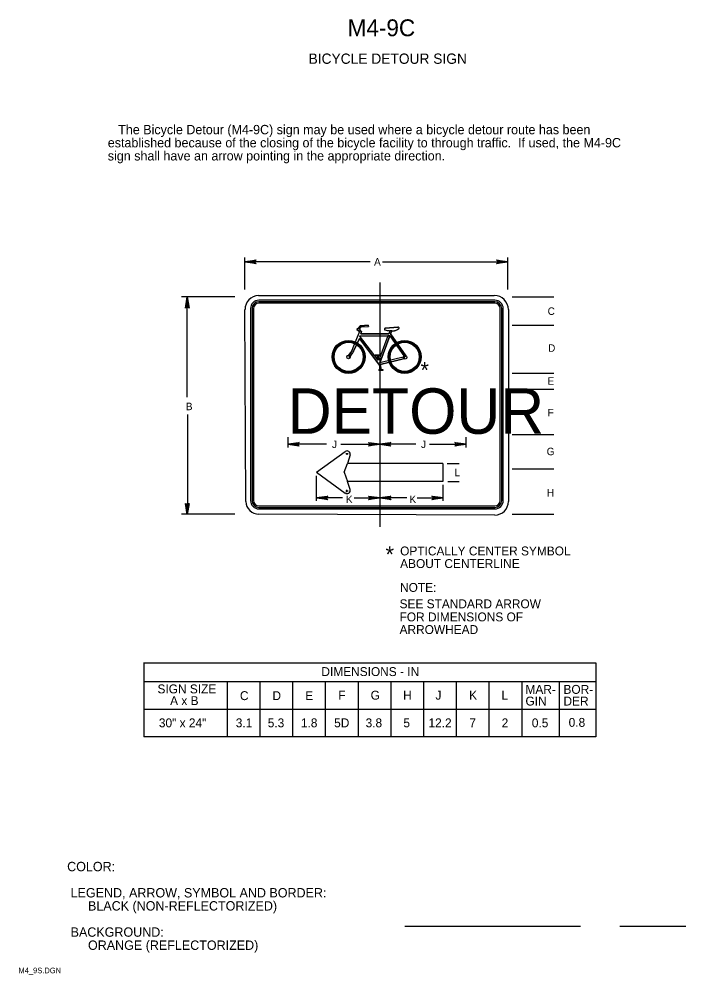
# Model space of a CAD drawing. Extents: x 0.012 to 0.191, y 0.004 to 0.259.
import ezdxf

# ---------------------------------------------------------------- set-up
doc = ezdxf.new("R2010")
doc.units = 0
for name, color, linetype in [('1', 7, 'Continuous'), ('2', 7, 'Continuous'), ('3', 7, 'Continuous')]:
    doc.layers.add(name, color=color, linetype=linetype)

# ---------------------------------------------------------------- blocks, each defined once
blk = doc.blocks.new('RARROW')
at = {"layer": '3'}
for p, q in [((-2.156, 0.28500000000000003), (-2.2665, 0.384625)), ((-2.2665, 0.384625), (0, 0)), ((0, 0), (-2.2665, -0.379125)), ((-2.156, 0.28500000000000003), (-2.075625, 0.12075)), ((0, 0), (-2.156, 0.28500000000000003)), ((-2.14975, -0.2705), (0, 0)), ((-2.075625, 0.12075), (0, 0)), ((0, 0), (-2.074, -0.108)), ((-2.2665, -0.379125), (-2.14975, -0.2705)), ((-2.074, -0.108), (-2.14975, -0.2705))]:
    blk.add_line(p, q, dxfattribs=at)

msp = doc.modelspace()

# ---------------------------------------------------------------- linework, layer by layer
at = {"layer": '1'}
for p, q in [((0.10875, 0.18887500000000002), (0.10875, 0.12356034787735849)), ((0.11543984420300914, 0.01694517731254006), (0.1624214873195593, 0.01694517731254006)), ((0.17295324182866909, 0.01694517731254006), (0.19056484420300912, 0.01694517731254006))]:
    msp.add_line(p, q, dxfattribs=at)
at = {"layer": '2'}
for p, q in [((0.076375, 0.185375), (0.139375, 0.185375)), ((0.1395, 0.184125), (0.0765, 0.184125)), ((0.073, 0.130375), (0.07275, 0.181625)), ((0.07425, 0.181875), (0.07425, 0.130625)), ((0.07465000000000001, 0.181875), (0.07465000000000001, 0.130625)), ((0.07505, 0.181875), (0.07505, 0.130625)), ((0.1395, 0.183725), (0.0765, 0.183725)), ((0.1395, 0.183325), (0.0765, 0.183325)), ((0.14095, 0.130625), (0.14095, 0.181875)), ((0.14135, 0.130625), (0.14135, 0.181875)), ((0.14175000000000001, 0.130625), (0.14175000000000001, 0.181875)), ((0.143125, 0.181625), (0.143125, 0.130375)), ((0.0765, 0.129175), (0.1395, 0.129175)), ((0.0765, 0.128775), (0.1395, 0.128775)), ((0.0765, 0.128375), (0.1395, 0.128375)), ((0.1395, 0.12675), (0.0765, 0.127)), ((0.04576275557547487, 0.08737500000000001), (0.04576275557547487, 0.06749703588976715)), ((0.04576275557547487, 0.0873220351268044), (0.16651708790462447, 0.0873220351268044)), ((0.16651708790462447, 0.0873220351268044), (0.16651708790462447, 0.06749703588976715)), ((0.16651708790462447, 0.08219703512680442), (0.04576275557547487, 0.08219703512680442)), ((0.06796555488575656, 0.08219416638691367), (0.06796555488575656, 0.06749703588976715)), ((0.07671555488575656, 0.08219416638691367), (0.07671555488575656, 0.06749703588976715)), ((0.08546555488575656, 0.08219416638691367), (0.08546555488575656, 0.06749703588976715)), ((0.09421555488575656, 0.08219416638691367), (0.09421555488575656, 0.06749703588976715)), ((0.10296555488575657, 0.08219416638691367), (0.10296555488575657, 0.06749703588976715)), ((0.11171555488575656, 0.08219416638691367), (0.11171555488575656, 0.06749703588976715)), ((0.12046555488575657, 0.08219416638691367), (0.12046555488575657, 0.06749703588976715)), ((0.1292155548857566, 0.08219416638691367), (0.1292155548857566, 0.06749703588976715)), ((0.13789974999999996, 0.08219416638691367), (0.13789974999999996, 0.06749703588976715)), ((0.14674055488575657, 0.08219416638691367), (0.14674055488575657, 0.06749703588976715)), ((0.15670470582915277, 0.08219416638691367), (0.15670470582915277, 0.06749703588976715)), ((0.16651708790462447, 0.07484703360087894), (0.04576275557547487, 0.07484703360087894)), ((0.16651708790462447, 0.06749703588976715), (0.04576275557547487, 0.06749703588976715))]:
    msp.add_line(p, q, dxfattribs=at)
for centre, radius, start, end in [((0.07647908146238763, 0.181684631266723), 0.00368802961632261, 90.97102222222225, 180.97102222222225), ((0.07648591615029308, 0.1818871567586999), 0.002235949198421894, 90.31151666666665, 180.31151666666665), ((0.1393750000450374, 0.18162500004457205), 0.0037499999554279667, 0, 90), ((0.13950000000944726, 0.1818750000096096), 0.0022499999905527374, 0, 90), ((0.07648591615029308, 0.1818871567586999), 0.0018359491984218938, 90.31151666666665, 180.31151666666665), ((0.07648591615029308, 0.1818871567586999), 0.0014359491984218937, 90.31151666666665, 180.31151666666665), ((0.13950000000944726, 0.1818750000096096), 0.0018499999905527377, 0, 90), ((0.13950000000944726, 0.1818750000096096), 0.0014499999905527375, 0, 90), ((0.07643750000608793, 0.13043750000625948), 0.0034380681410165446, 181.04162777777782, 271.0416277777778), ((0.07650000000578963, 0.13062500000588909), 0.002250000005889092, 180, 270), ((0.07650000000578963, 0.13062500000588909), 0.001850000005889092, 180, 270), ((0.07650000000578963, 0.13062500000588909), 0.0014500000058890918, 180, 270), ((0.13949999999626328, 0.130625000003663), 0.00225000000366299, 270, 0), ((0.13949999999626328, 0.130625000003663), 0.0018500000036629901, 270, 0), ((0.13949999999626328, 0.130625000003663), 0.00145000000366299, 270, 0), ((0.13949999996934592, 0.13037500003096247), 0.003625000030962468, 270, 0)]:
    msp.add_arc(centre, radius, start, end, dxfattribs=at)
at = {"layer": '3'}
for p, q in [((0.07274167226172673, 0.18700966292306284), (0.07274167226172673, 0.19550966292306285)), ((0.10625, 0.194375), (0.07275, 0.194375)), ((0.1095, 0.194375), (0.14300000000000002, 0.194375)), ((0.14299612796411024, 0.18700966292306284), (0.14299612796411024, 0.19550966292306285)), ((0.07008239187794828, 0.18499713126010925), (0.0557621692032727, 0.18499713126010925)), ((0.05733301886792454, 0.15821797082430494), (0.05733301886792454, 0.185)), ((0.144125, 0.185), (0.15525, 0.185)), ((0.10267941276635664, 0.17630164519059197), (0.10325303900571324, 0.17687527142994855)), ((0.10331677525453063, 0.17572801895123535), (0.10267941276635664, 0.17630164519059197)), ((0.10325303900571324, 0.17687527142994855), (0.10338051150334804, 0.17713021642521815)), ((0.10331677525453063, 0.17636538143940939), (0.10357172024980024, 0.17662032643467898)), ((0.10389040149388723, 0.1757917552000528), (0.10331677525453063, 0.17636538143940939)), ((0.10338051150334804, 0.17713021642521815), (0.10350798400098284, 0.17725768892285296)), ((0.10350798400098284, 0.17725768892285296), (0.10369919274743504, 0.17732142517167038)), ((0.10357172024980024, 0.17662032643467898), (0.10376292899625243, 0.17700274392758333)), ((0.10363545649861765, 0.1767477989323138), (0.10376292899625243, 0.17700274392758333)), ((0.10369919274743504, 0.17732142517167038), (0.10567501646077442, 0.1774488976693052)), ((0.10376292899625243, 0.17700274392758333), (0.10573875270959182, 0.17713021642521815)), ((0.10567501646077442, 0.1774488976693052), (0.10573875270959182, 0.17713021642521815)), ((0.1102640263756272, 0.17662032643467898), (0.11364204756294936, 0.17693900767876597)), ((0.144125, 0.1774488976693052), (0.15525, 0.1774488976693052)), ((0.10331677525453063, 0.17572801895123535), (0.10159589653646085, 0.17139395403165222)), ((0.10331677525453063, 0.17387966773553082), (0.10210578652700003, 0.1712027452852)), ((0.1086706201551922, 0.16680494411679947), (0.10331677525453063, 0.17387966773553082)), ((0.10338051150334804, 0.1746445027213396), (0.11096512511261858, 0.1746445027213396)), ((0.1083519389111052, 0.16814340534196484), (0.10338051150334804, 0.1746445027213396)), ((0.10389040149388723, 0.1757917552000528), (0.10369919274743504, 0.1751543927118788)), ((0.10369919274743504, 0.1751543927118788), (0.11115633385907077, 0.1751543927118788)), ((0.11096512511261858, 0.1746445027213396), (0.10854314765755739, 0.16807966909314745)), ((0.11147501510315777, 0.1745807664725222), (0.108798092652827, 0.16744230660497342)), ((0.11147501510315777, 0.1759192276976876), (0.11115633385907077, 0.1751543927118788)), ((0.11147501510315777, 0.1745807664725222), (0.11536292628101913, 0.16897197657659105)), ((0.11198490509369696, 0.1759192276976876), (0.11166622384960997, 0.1751543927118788)), ((0.11166622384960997, 0.1751543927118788), (0.11574534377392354, 0.16929065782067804)), ((0.10758710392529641, 0.16948186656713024), (0.10803325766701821, 0.16948186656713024)), ((0.10758710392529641, 0.16948186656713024), (0.10758710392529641, 0.16935439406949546)), ((0.10758710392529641, 0.16935439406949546), (0.10803325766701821, 0.16935439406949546)), ((0.10803325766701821, 0.16948186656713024), (0.1087343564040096, 0.16948186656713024)), ((0.10803325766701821, 0.16935439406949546), (0.1083519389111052, 0.16814340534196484)), ((0.1082244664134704, 0.16935439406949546), (0.10854314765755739, 0.16807966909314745)), ((0.1082244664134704, 0.16935439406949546), (0.1087343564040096, 0.16935439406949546)), ((0.1087343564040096, 0.16948186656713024), (0.1087343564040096, 0.16935439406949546)), ((0.11536292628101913, 0.16897197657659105), (0.108798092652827, 0.16744230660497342)), ((0.1086706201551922, 0.16680494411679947), (0.10898930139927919, 0.16553021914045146)), ((0.10875, 0.16557287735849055), (0.10875, 0.16657287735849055)), ((0.11523545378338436, 0.16846208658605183), (0.10886182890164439, 0.16693241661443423)), ((0.10886182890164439, 0.16693241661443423), (0.1091805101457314, 0.16553021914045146)), ((0.10854314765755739, 0.16553021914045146), (0.10898930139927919, 0.16553021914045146)), ((0.10854314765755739, 0.16540274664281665), (0.10854314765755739, 0.16553021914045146)), ((0.10854314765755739, 0.16540274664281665), (0.10898930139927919, 0.16540274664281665)), ((0.10898930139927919, 0.16540274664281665), (0.10969040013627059, 0.16540274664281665)), ((0.1091805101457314, 0.16553021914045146), (0.10969040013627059, 0.16553021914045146)), ((0.10969040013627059, 0.16540274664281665), (0.10969040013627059, 0.16553021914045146)), ((0.144125, 0.1645948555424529), (0.15525, 0.1645948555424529)), ((0.144125, 0.1603503), (0.15525, 0.1603503)), ((0.05737460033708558, 0.1535789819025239), (0.05737460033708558, 0.12699713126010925)), ((0.144125, 0.1482703), (0.15525, 0.1482703)), ((0.08425993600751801, 0.14477478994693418), (0.08425993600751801, 0.1475572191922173)), ((0.0945422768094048, 0.1456405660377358), (0.08425993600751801, 0.1456405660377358)), ((0.0983491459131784, 0.1456405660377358), (0.10875, 0.1456405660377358)), ((0.11844587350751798, 0.1456405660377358), (0.10875, 0.1456405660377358)), ((0.12210097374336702, 0.1456405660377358), (0.13119375, 0.1456405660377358)), ((0.1318394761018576, 0.14477478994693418), (0.1318394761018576, 0.1475572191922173)), ((0.09186034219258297, 0.1382025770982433), (0.09952695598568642, 0.14370253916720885)), ((0.10036028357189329, 0.14311920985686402), (0.09969362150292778, 0.14311920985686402)), ((0.1002769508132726, 0.14310866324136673), (0.09969362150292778, 0.14310866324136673)), ((0.09994361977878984, 0.14327532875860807), (0.09994361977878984, 0.14285866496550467)), ((0.09994361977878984, 0.1432025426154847), (0.09994361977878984, 0.14286921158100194)), ((0.09927695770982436, 0.13820257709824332), (0.10011028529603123, 0.14053589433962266)), ((0.10086028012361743, 0.14278587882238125), (0.10011028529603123, 0.14053589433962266)), ((0.12566667, 0.14053589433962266), (0.10011028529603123, 0.14053589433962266)), ((0.12566667, 0.14053589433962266), (0.12566667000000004, 0.13570259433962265)), ((0.12675996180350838, 0.14053589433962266), (0.12999769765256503, 0.14053589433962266)), ((0.09186034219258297, 0.1382025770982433), (0.09952695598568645, 0.1326192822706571)), ((0.09927695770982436, 0.13820257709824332), (0.10011028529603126, 0.13570259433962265)), ((0.144125, 0.1390703), (0.15525, 0.1390703)), ((0.09186735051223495, 0.1305061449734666), (0.09186735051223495, 0.1372582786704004)), ((0.10086028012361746, 0.1335359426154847), (0.10011028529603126, 0.13570259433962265)), ((0.12566667, 0.13570259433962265), (0.10011028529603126, 0.13570259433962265)), ((0.12696232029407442, 0.13570259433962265), (0.12999769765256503, 0.13570259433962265)), ((0.10036028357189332, 0.13311927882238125), (0.09969362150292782, 0.13311927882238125)), ((0.10027695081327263, 0.13310873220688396), (0.09969362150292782, 0.13310873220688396)), ((0.09994361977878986, 0.13303594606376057), (0.09994361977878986, 0.13345260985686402)), ((0.09994361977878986, 0.1328587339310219), (0.09994361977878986, 0.13335873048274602)), ((0.12572445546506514, 0.1305061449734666), (0.12572445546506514, 0.13481732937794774)), ((0.0988234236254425, 0.13132370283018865), (0.09186735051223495, 0.13132370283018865)), ((0.1018967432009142, 0.13132370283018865), (0.10875, 0.13132370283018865)), ((0.11601124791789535, 0.13132370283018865), (0.10875, 0.13132370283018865)), ((0.11876838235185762, 0.13132370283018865), (0.12572445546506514, 0.13132370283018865)), ((0.07008239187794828, 0.12699713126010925), (0.0557621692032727, 0.12699713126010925)), ((0.144125, 0.1269903), (0.15525, 0.1269903))]:
    msp.add_line(p, q, dxfattribs=at)
for points in [[(0.11574534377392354, 0.16929065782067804), (0.11166622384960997, 0.1751543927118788), (0.11198490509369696, 0.1759192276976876), (0.11147501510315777, 0.1759192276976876), (0.11115633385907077, 0.1751543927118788), (0.10369919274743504, 0.1751543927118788), (0.10389040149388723, 0.1757917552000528), (0.10331677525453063, 0.17636538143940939), (0.10357172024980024, 0.17662032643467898), (0.10376292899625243, 0.17700274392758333), (0.10573875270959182, 0.17713021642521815), (0.10567501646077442, 0.1774488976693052), (0.10369919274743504, 0.17732142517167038), (0.10350798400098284, 0.17725768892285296), (0.10338051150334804, 0.17713021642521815), (0.10325303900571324, 0.17687527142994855), (0.10267941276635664, 0.17630164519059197), (0.10331677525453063, 0.17572801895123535), (0.10159589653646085, 0.17139395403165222), (0.10140468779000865, 0.1708203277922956), (0.10121347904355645, 0.17043791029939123), (0.10083106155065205, 0.16986428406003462), (0.10038490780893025, 0.16935439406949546), (0.10083106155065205, 0.16909944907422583), (0.10102227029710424, 0.16935439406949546), (0.10146842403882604, 0.16986428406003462), (0.10185084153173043, 0.17056538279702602), (0.10210578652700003, 0.1712027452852), (0.10331677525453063, 0.17387966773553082), (0.1086706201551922, 0.16680494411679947), (0.10898930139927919, 0.16553021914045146), (0.10854314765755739, 0.16553021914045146), (0.10854314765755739, 0.16540274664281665), (0.10969040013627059, 0.16540274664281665), (0.10969040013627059, 0.16553021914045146), (0.1091805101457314, 0.16553021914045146), (0.10886182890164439, 0.16693241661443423), (0.11536292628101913, 0.16852582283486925), (0.11536292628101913, 0.16897197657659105), (0.108798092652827, 0.16744230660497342), (0.11147501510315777, 0.1745807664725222), (0.11096512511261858, 0.1746445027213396), (0.10854314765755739, 0.16807966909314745), (0.1082244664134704, 0.16935439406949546), (0.1087343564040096, 0.16935439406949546), (0.1087343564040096, 0.16948186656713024), (0.10758710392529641, 0.16948186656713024), (0.10758710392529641, 0.16935439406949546), (0.10803325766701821, 0.16935439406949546), (0.1083519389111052, 0.16814340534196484), (0.10338051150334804, 0.1746445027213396), (0.11147501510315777, 0.1745807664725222), (0.11536292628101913, 0.16897197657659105)], [(0.11364204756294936, 0.17693900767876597), (0.1102640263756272, 0.17662032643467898), (0.11020029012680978, 0.17662032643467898), (0.110072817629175, 0.17655659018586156), (0.11000908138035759, 0.17642911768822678), (0.110072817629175, 0.17623790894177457), (0.11020029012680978, 0.17617417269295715), (0.11071018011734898, 0.1760467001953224), (0.11153875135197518, 0.1759192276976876), (0.11236732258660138, 0.1759192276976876), (0.11274974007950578, 0.17598296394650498), (0.11294094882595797, 0.1760467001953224), (0.11319589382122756, 0.17611043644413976), (0.11351457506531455, 0.17630164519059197), (0.11383325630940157, 0.17649285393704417), (0.11389699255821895, 0.17655659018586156), (0.11396072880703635, 0.17662032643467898), (0.11396072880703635, 0.1767477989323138), (0.11389699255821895, 0.17687527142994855), (0.11376952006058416, 0.17693900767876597)]]:
    msp.add_lwpolyline(points, close=True, dxfattribs=at)
for centre, radius in [((0.10044849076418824, 0.1689904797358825), 0.004397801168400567), ((0.10044849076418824, 0.1689904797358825), 0.004346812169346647), ((0.10044849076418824, 0.1689904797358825), 0.004295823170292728), ((0.10044849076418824, 0.1689904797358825), 0.004244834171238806), ((0.10044849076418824, 0.1689904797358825), 0.004193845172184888), ((0.10044849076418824, 0.1689904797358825), 0.004142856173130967), ((0.10044849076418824, 0.1689904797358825), 0.004091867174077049), ((0.10044849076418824, 0.1689904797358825), 0.004040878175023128), ((0.10044849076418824, 0.1689904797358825), 0.00398988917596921), ((0.10044849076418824, 0.1689904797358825), 0.003938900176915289), ((0.10044849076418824, 0.1689904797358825), 0.00388791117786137), ((0.11542650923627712, 0.1689904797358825), 0.004397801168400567), ((0.11542650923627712, 0.1689904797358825), 0.004346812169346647), ((0.11542650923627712, 0.1689904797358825), 0.004295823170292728), ((0.11542650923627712, 0.1689904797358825), 0.004244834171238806), ((0.11542650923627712, 0.1689904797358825), 0.004193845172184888), ((0.11542650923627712, 0.1689904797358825), 0.004142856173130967), ((0.11542650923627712, 0.1689904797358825), 0.004091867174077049), ((0.11542650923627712, 0.1689904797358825), 0.004040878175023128), ((0.11542650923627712, 0.1689904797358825), 0.00398988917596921), ((0.11542650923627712, 0.1689904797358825), 0.003938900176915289), ((0.11542650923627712, 0.1689904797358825), 0.00388791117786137), ((0.10044849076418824, 0.1689904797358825), 0.00048540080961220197), ((0.11555398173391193, 0.16886300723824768), 0.00048540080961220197)]:
    msp.add_circle(centre, radius, dxfattribs=at)
for centre, radius, start, end in [((0.11023200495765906, 0.1764157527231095), 0.00022534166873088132, 81.86989722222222, 261.8698972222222), ((0.11217596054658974, 0.18368965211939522), 0.00775296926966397, 255.23545833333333, 270.9420861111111), ((0.11207456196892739, 0.17882034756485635), 0.002891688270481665, 274.53958888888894, 309.0632305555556), ((0.09646926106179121, 0.17319425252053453), 0.005461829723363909, 312.61111111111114, 340.70747500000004), ((0.09646926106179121, 0.17319425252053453), 0.0059717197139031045, 312.61111111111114, 340.70747500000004), ((0.10004468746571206, 0.1430170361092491), 0.0008506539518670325, 343.4926194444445, 127.49033611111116), ((0.10004659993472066, 0.13331141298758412), 0.0008506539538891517, 232.50966388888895, 16.507380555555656)]:
    msp.add_arc(centre, radius, start, end, dxfattribs=at)

# ---------------------------------------------------------------- block references
at = {"layer": '3', "xscale": 0.0013236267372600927, "yscale": 0.001309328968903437}
for p, rotation in [((0.07275, 0.194375), 180), ((0.05733301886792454, 0.185), 90), ((0.08425993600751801, 0.1456405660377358), 180), ((0.10875, 0.1456405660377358), 180), ((0.09186735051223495, 0.13132370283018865), 180), ((0.10875, 0.13132370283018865), 180), ((0.05733301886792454, 0.12687500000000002), -90)]:
    msp.add_blockref('RARROW', p, dxfattribs=dict(at, rotation=rotation))
for p in [(0.14300000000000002, 0.194375), (0.10875, 0.1456405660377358), (0.1318394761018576, 0.1456405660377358), (0.10875, 0.13132370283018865), (0.12572445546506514, 0.13132370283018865)]:
    msp.add_blockref('RARROW', p, dxfattribs=at)

# ---------------------------------------------------------------- texts
at = {"layer": '1'}
for s, height, p in [('M4-9C', 0.0045000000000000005, (0.10018477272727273, 0.254625)), ('BICYCLE DETOUR SIGN', 0.00275025, (0.0897534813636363, 0.24725)), ('*', 0.004332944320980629, (0.11965541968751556, 0.16330399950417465)), ('DETOUR', 0.01213425, (0.08418428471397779, 0.14844787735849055)), ('*', 0.004332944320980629, (0.11032163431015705, 0.11408029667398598)), ('OPTICALLY CENTER SYMBOL', 0.0023752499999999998, (0.11421851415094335, 0.1159663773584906)), ('ABOUT CENTERLINE', 0.0023752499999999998, (0.11421851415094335, 0.11259112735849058)), ('NOTE:', 0.0023752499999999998, (0.11419174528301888, 0.10622712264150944)), ('SEE STANDARD ARROW', 0.0023752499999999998, (0.11406674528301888, 0.10185212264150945)), ('FOR DIMENSIONS OF', 0.0023752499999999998, (0.11406674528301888, 0.09835212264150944)), ('ARROWHEAD', 0.0023752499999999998, (0.11406674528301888, 0.09497712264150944)), ('MAR-', 0.0023752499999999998, (0.14770691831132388, 0.079)), ('BOR-', 0.0023752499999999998, (0.15785868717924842, 0.079)), ('GIN', 0.0023752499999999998, (0.14770691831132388, 0.075875)), ('DER', 0.0023752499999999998, (0.15785868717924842, 0.075875)), ('COLOR:', 0.0024997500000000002, (0.02525, 0.031624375)), (' LEGEND, ARROW, SYMBOL AND BORDER:', 0.0024997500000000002, (0.02525, 0.024624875)), ('      BLACK (NON-REFLECTORIZED)', 0.0024997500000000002, (0.02525, 0.021125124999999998)), (' BACKGROUND:', 0.0024997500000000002, (0.02525, 0.014125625)), ('      ORANGE (REFLECTORIZED)', 0.0024997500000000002, (0.02525, 0.010625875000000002)), ('M4_9S.DGN', 0.0015, (0.01225, 0.004375))]:
    msp.add_text(s, height=height, dxfattribs=at).set_placement(p)
at = {"layer": '2'}
for s, height, p in [('   The Bicycle Detour (M4-9C) sign may be used where a bicycle detour route has been ', 0.0024997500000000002, (0.03610613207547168, 0.22843891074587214)), ('established because of the closing of the bicycle facility to through traffic.  If used, the M4-9C ', 0.0024997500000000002, (0.03610613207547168, 0.22493916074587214)), ('sign shall have an arrow pointing in the appropriate direction. ', 0.0024997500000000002, (0.03610613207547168, 0.22143941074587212)), ('DIMENSIONS - IN', 0.0023752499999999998, (0.0931822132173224, 0.08375)), ('SIGN SIZE', 0.0023752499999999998, (0.04938775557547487, 0.079125)), ('C', 0.0023752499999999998, (0.07141595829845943, 0.07732417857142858)), ('D', 0.0023752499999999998, (0.08009732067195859, 0.07732417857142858)), ('E', 0.0023752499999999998, (0.08887984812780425, 0.07732417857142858)), ('F', 0.0023752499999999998, (0.09768519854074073, 0.07744917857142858)), ('G', 0.0023752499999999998, (0.10633934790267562, 0.07744917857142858)), ('H', 0.0023752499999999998, (0.11501546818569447, 0.07744917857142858)), ('J', 0.0023752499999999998, (0.12366164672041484, 0.07744917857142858)), ('K', 0.0023752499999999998, (0.13265052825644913, 0.07744917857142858)), ('L', 0.0023752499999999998, (0.14127927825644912, 0.07744917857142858)), ('A x B', 0.0023752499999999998, (0.05276275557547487, 0.076))]:
    msp.add_text(s, height=height, dxfattribs=at).set_placement(p)
at = {"layer": '3'}
for s, height, p in [('A', 0.00200025, (0.10725, 0.193375)), ('C', 0.00200025, (0.153625, 0.1802017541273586)), ('D', 0.00200025, (0.15375, 0.17034040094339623)), ('E', 0.00200025, (0.15358719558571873, 0.16154129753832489)), ('B', 0.00200025, (0.05695801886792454, 0.15475)), ('F', 0.00200025, (0.15362303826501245, 0.15310547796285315)), ('J', 0.002, (0.0960089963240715, 0.1446405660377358)), ('J', 0.002, (0.11979876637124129, 0.1446405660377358)), ('G', 0.00200025, (0.153375, 0.1427197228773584)), ('L', 0.002, (0.1287415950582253, 0.13712800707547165)), ('H', 0.00200025, (0.1534299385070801, 0.13169118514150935)), ('K', 0.002, (0.09974165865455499, 0.1299472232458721)), ('K', 0.002, (0.1167161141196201, 0.12995987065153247)), ('30" x 24"', 0.0023752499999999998, (0.04975816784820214, 0.07006237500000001)), ('3.1', 0.0023752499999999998, (0.07030606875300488, 0.07006237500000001)), ('5.3', 0.0023752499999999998, (0.07884311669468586, 0.07006237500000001)), ('1.8', 0.0023752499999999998, (0.08770133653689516, 0.07006237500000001)), ('5D', 0.0023752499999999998, (0.09659186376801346, 0.07006237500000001)), ('3.8', 0.0023752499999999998, (0.10498941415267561, 0.07006237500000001)), ('5', 0.0023752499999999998, (0.1150849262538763, 0.07006237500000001)), ('12.2', 0.0023752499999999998, (0.12179349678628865, 0.07006237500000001)), ('7', 0.0023752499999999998, (0.1327035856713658, 0.07006237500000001)), ('2', 0.0023752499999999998, (0.14134817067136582, 0.07006237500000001)), ('0.5', 0.0023752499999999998, (0.14940272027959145, 0.07006237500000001)), ('0.8', 0.0023752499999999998, (0.15924101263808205, 0.07018737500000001))]:
    msp.add_text(s, height=height, dxfattribs=at).set_placement(p)

doc.saveas('drawing.dxf')
